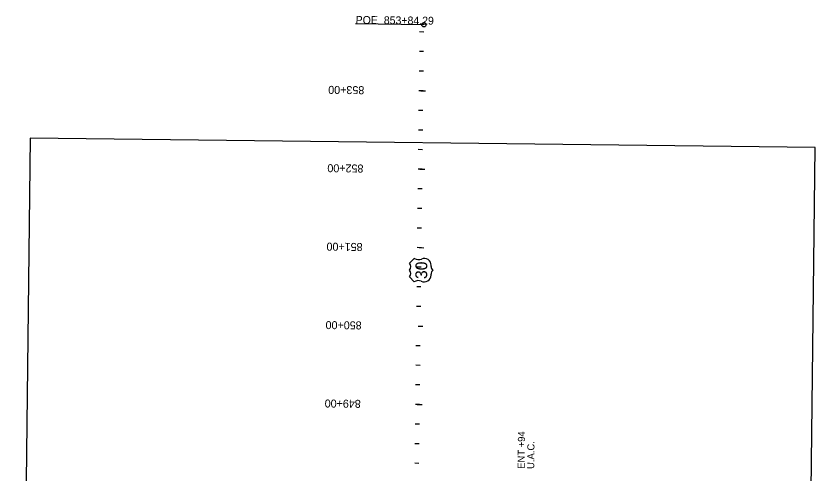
# Model space of a CAD drawing. Extents: x 16507806 to 16508824, y 7132703 to 7134669.
# Drawn here: x 16507806 to 16508824, y 7134086 to 7134669 of the extents above; entities that cross this region are included whole.
import ezdxf

# ---------------------------------------------------------------- set-up
doc = ezdxf.new("R2010")
doc.units = 0
for name, color, linetype in [('dsnCellsHighwaySymbols', 7, 'Continuous'), ('NamedBoundary', 7, 'Continuous'), ('Text', 7, 'Continuous'), ('TextAlignment', 7, 'Continuous'), ('TextAlignmentLrg', 7, 'Continuous'), ('TextAlignmentSml', 7, 'Continuous')]:
    doc.layers.add(name, color=color, linetype=linetype)

msp = doc.modelspace()

# ---------------------------------------------------------------- linework, layer by layer
at = {"layer": 'dsnCellsHighwaySymbols'}
for p, q in [((16508313.7, 7134359.9), (16508307.4, 7134353.7)), ((16508313.7, 7134359.9), (16508307.4, 7134353.7)), ((16508334.8, 7134349.6), (16508334.9, 7134350.9)), ((16508334.8, 7134349.6), (16508334.9, 7134350.9)), ((16508307.2, 7134336.2), (16508313.4, 7134329.9)), ((16508307.2, 7134336.2), (16508313.4, 7134329.9)), ((16508334.7, 7134338.4), (16508334.7, 7134339.6)), ((16508334.7, 7134338.4), (16508334.7, 7134339.6))]:
    msp.add_line(p, q, dxfattribs=at)
for centre, radius, start, end in [((16508302.9, 7134349.4), 6.25, 314.9199, 43.7742), ((16508302.9, 7134349.4), 6.25, 314.9199, 43.7742), ((16508318.9, 7134366.9), 8.75, 233.6843, 294.3571), ((16508318.9, 7134366.9), 8.75, 233.6843, 294.3571), ((16508326.1, 7134351), 8.75, 359.3471, 114.3575), ((16508326.1, 7134351), 8.75, 359.3471, 114.3575), ((16508302.8, 7134340.6), 6.25, 314.9199, 43.7742), ((16508302.8, 7134340.6), 6.25, 314.9199, 43.7742), ((16508341, 7134339.6), 6.25, 126.2169, 179.3472), ((16508341, 7134339.6), 6.25, 126.2169, 179.3472), ((16508341.1, 7134349.6), 6.25, 179.3472, 232.477), ((16508341.1, 7134349.6), 6.25, 179.3472, 232.477), ((16508318.4, 7134322.7), 8.75, 64.3365, 125.0099), ((16508318.4, 7134322.7), 8.75, 64.3365, 125.0099), ((16508326, 7134338.5), 8.75, 244.3367, 359.3471), ((16508326, 7134338.5), 8.75, 244.3367, 359.3471)]:
    msp.add_arc(centre, radius, start, end, dxfattribs=at)
at = {"layer": 'NamedBoundary'}
msp.add_lwpolyline([(16507805.9, 7132945.5), (16508805.8, 7132934), (16508823.9, 7134501.4), (16507824, 7134512.9)], close=True, dxfattribs=at)
at = {"layer": 'TextAlignment'}
msp.add_line((16508325.6, 7134657.7), (16508238.6, 7134658.7), dxfattribs=at)
msp.add_circle((16508325.6, 7134657.7), 2.67, dxfattribs=at)
at = {"layer": 'TextAlignmentLrg'}
for p, q in [((16508324.7, 7134573.4), (16508319.2, 7134573.5)), ((16508323.5, 7134473.4), (16508318.1, 7134473.5)), ((16508322.4, 7134373.4), (16508317, 7134373.5)), ((16508318.2, 7134273.5), (16508324.3, 7134273.4)), ((16508320.2, 7134173.4), (16508314.7, 7134173.5))]:
    msp.add_line(p, q, dxfattribs=at)
at = {"layer": 'TextAlignmentSml'}
for p, q in [((16508325.5, 7134648.4), (16508320, 7134648.5)), ((16508325.2, 7134623.4), (16508319.8, 7134623.5)), ((16508324.9, 7134598.4), (16508319.5, 7134598.5)), ((16508321.6, 7134573.4), (16508327.7, 7134573.4)), ((16508324.4, 7134548.4), (16508318.9, 7134548.5)), ((16508324.1, 7134523.4), (16508318.6, 7134523.5)), ((16508323.8, 7134498.4), (16508318.4, 7134498.5)), ((16508320.5, 7134473.4), (16508326.6, 7134473.4)), ((16508323.3, 7134448.4), (16508317.8, 7134448.5)), ((16508323, 7134423.4), (16508317.5, 7134423.5)), ((16508322.7, 7134398.4), (16508317.2, 7134398.5)), ((16508319.4, 7134373.5), (16508325.5, 7134373.4)), ((16508322.1, 7134348.4), (16508316.7, 7134348.5)), ((16508321.8, 7134323.4), (16508316.4, 7134323.5)), ((16508321.6, 7134298.4), (16508316.1, 7134298.5)), ((16508318.2, 7134273.5), (16508324.3, 7134273.4)), ((16508321, 7134248.4), (16508315.5, 7134248.5)), ((16508320.7, 7134223.4), (16508315.3, 7134223.5)), ((16508320.4, 7134198.4), (16508315, 7134198.5)), ((16508317.1, 7134173.5), (16508323.2, 7134173.4)), ((16508319.9, 7134148.4), (16508314.4, 7134148.5)), ((16508319.6, 7134123.4), (16508314.1, 7134123.5)), ((16508319.3, 7134098.4), (16508313.9, 7134098.5))]:
    msp.add_line(p, q, dxfattribs=at)

# ---------------------------------------------------------------- texts
at = {"layer": 'dsnCellsHighwaySymbols'}
msp.add_text('30', height=15, rotation=89.347, dxfattribs=at).set_placement((16508329.7, 7134333.4))
at = {"layer": 'Text'}
for s, p in [('ENT +94', (16508453.9, 7134091.4)), ('U.A.C.', (16508466.1, 7134091.3))]:
    msp.add_text(s, height=9, rotation=89.347, dxfattribs=at).set_placement(p)
at = {"layer": 'TextAlignment'}
for s, p in [('POE ', (16508238.6, 7134658.9)), ('853+84.29', (16508274.5, 7134658.5))]:
    msp.add_text(s, height=10.02, rotation=359.3566, dxfattribs=at).set_placement(p)
at = {"layer": 'TextAlignmentLrg'}
msp.add_text('850+00', height=10.2, rotation=179.3566, dxfattribs=at).set_placement((16508246.3, 7134279.4))
at = {"layer": 'TextAlignmentSml'}
for s, p in [('853+00', (16508249.7, 7134579.3)), ('852+00', (16508248.6, 7134479.4)), ('851+00', (16508247.5, 7134379.4)), ('850+00', (16508246.3, 7134279.4)), ('849+00', (16508245.2, 7134179.4))]:
    msp.add_text(s, height=10.2, rotation=179.3566, dxfattribs=at).set_placement(p)

doc.saveas('drawing.dxf')
